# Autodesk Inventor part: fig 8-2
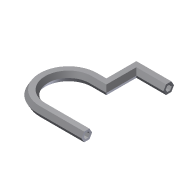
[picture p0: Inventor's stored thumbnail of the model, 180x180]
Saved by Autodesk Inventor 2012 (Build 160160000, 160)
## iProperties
Created: 2004-05
Part Number: fig 8-2
Document SubType Name: Modeling
Designer: CADCIM Technologies
Manufacturer: Standard
Standards Organization: Custom
Density: 1 g/cm^3
Material: Default
Author: CADCIM Technologies
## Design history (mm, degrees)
sketch "Sketch1"
  geometry: L1 (-42.583, 3.219)-(-90.066, 3.219); L2 (-90.066, 58.92)-(-77.282, 58.92); L3 (-77.282, 58.92)-(-77.282, 91.063); L4 (-77.282, 91.063)-(-42.583, 91.063); A1 r 27.851 centre (-90.066, 31.07) between (-90.066, 58.92) and (-90.066, 3.219)
  constraints: 8 end point, 2 parallel, 2 point on circle, 2 tangent, 1 centre point, 1 perpendicular
workplane "Work Plane2"
sketch "Sketch5"
  geometry: L1 (-5.697, 0)-(-2.849, 4.934); L2 (-2.849, 4.934)-(2.849, 4.934); L3 (2.849, 4.934)-(5.697, 0); L4 (5.697, 0)-(2.849, -4.934); L5 (2.849, -4.934)-(-2.849, -4.934); L6 (-2.849, -4.934)-(-5.697, 0); L7 (-3.256, 0)-(-1.628, 2.819); L8 (-1.628, 2.819)-(1.628, 2.819); L9 (1.628, 2.819)-(3.256, 0); L10 (3.256, 0)-(1.628, -2.819); L11 (1.628, -2.819)-(-1.628, -2.819); L12 (-1.628, -2.819)-(-3.256, 0); 2 further points
  constraints: 24 end point, 1 coincident, 22 other
sweep "Sweep4" sketch "Sketch5" dims "d3" = 0
body "Solid1"
